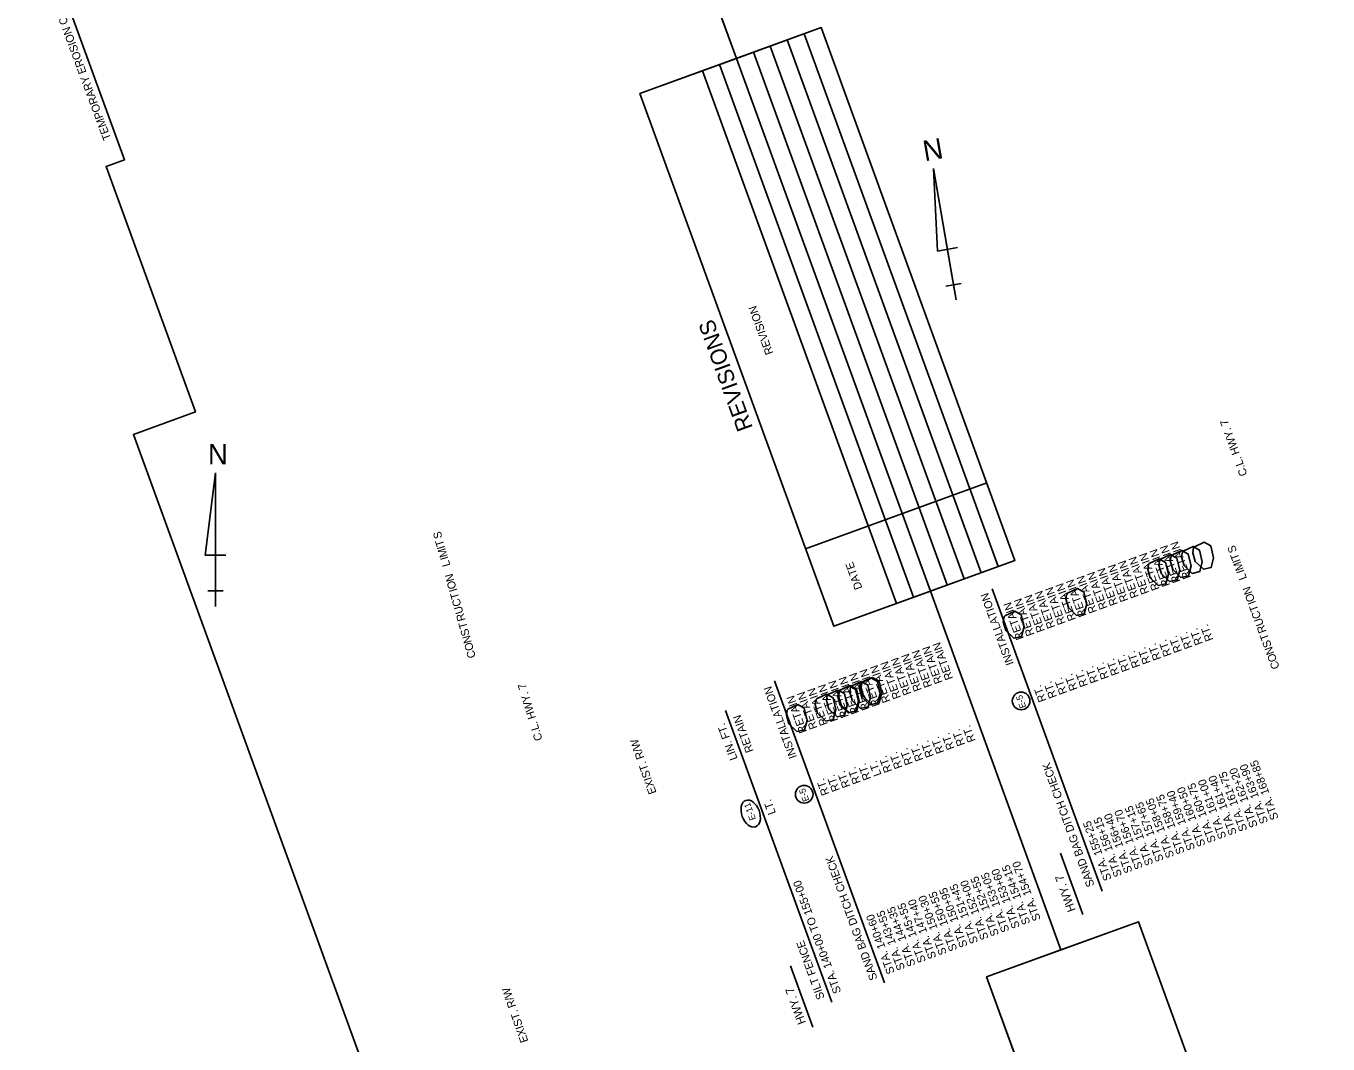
# Model space of a CAD drawing. Extents: x 986289 to 987754, y 1870781 to 1872971.
# Drawn here: x 986289 to 987265, y 1871771 to 1872534 of the extents above; entities that cross this region are included whole.
import ezdxf

# ---------------------------------------------------------------- set-up
doc = ezdxf.new("R2010")
doc.units = 0
for name, color, linetype in [('1', 7, 'Continuous'), ('44', 7, 'Continuous'), ('63', 7, 'Continuous'), ('Default', 7, 'Continuous'), ('NO PLOT', 7, 'Continuous'), ('R_Draft', 7, 'Continuous'), ('S_TREE', 7, 'Continuous')]:
    doc.layers.add(name, color=color, linetype=linetype)

msp = doc.modelspace()

# ---------------------------------------------------------------- linework, layer by layer
at = {"layer": '1'}
for p, q in [((986821.23, 1872510.15), (986718.28, 1872792.99)), ((987064.47, 1871841.86), (986966.59, 1872110.78)), ((987122.5, 1871862.99), (987008.75, 1871821.58)), ((987125.95, 1871499.59), (987008.75, 1871821.58))]:
    msp.add_line(p, q, dxfattribs=at)
msp.add_lwpolyline([(987207.82, 1871529.39), (987239.7, 1871540.99), (987122.5, 1871862.99)], dxfattribs=at)
for centre in [(987034.63, 1872028.46), (986872.01, 1871958.49)]:
    msp.add_circle(centre, 6.61, dxfattribs=at)
msp.add_ellipse((986831.89, 1871944.03), major_axis=(-3.6, 9.89), ratio=0.638788, dxfattribs=at)
at = {"layer": '44'}
for p, q in [((987095.25, 1871885.98), (987012.82, 1872112.45)), ((986932.24, 1871817.06), (986849.81, 1872043.53)), ((986892.62, 1871802.64), (986813, 1872021.4)), ((987080.79, 1871868.41), (987064.09, 1871914.31)), ((986878.55, 1871784.02), (986861.84, 1871829.92))]:
    msp.add_line(p, q, dxfattribs=at)
at = {"layer": '63'}
for p, q in [((986985.91, 1872329.1), (986969.03, 1872427.66)), ((986969.03, 1872427.66), (986982.01, 1872351.84)), ((986969.03, 1872427.66), (986971.83, 1872365.71)), ((986971.83, 1872365.71), (986987, 1872368.31)), ((986985.91, 1872329.1), (986982.01, 1872351.84)), ((986978.27, 1872339.5), (986989.65, 1872341.44)), ((986983.96, 1872340.47), (986978.27, 1872339.5)), ((986985.91, 1872329.1), (986983.96, 1872340.47)), ((986430.69, 1872199.39), (986422.99, 1872137.85)), ((986430.69, 1872099.39), (986430.69, 1872199.39)), ((986430.69, 1872199.39), (986430.69, 1872122.46)), ((986422.99, 1872137.85), (986438.38, 1872137.85)), ((986430.69, 1872099.39), (986430.69, 1872122.46)), ((986430.69, 1872110.93), (986424.92, 1872110.93)), ((986424.92, 1872110.93), (986436.46, 1872110.93)), ((986430.69, 1872099.39), (986430.69, 1872110.93))]:
    msp.add_line(p, q, dxfattribs=at)
at = {"layer": 'Default'}
for p, q in [((986748.87, 1872483.82), (986884.66, 1872533.24)), ((987017.33, 1872129.25), (986871.97, 1872528.62)), ((987030.02, 1872133.87), (986884.66, 1872533.24)), ((986991.96, 1872120.02), (986846.6, 1872519.39)), ((987004.65, 1872124.63), (986859.29, 1872524)), ((986966.59, 1872110.78), (986821.23, 1872510.15)), ((986979.27, 1872115.4), (986833.92, 1872514.77)), ((986979.27, 1872115.4), (986833.92, 1872514.77)), ((986941.22, 1872101.55), (986795.86, 1872500.92)), ((986953.9, 1872106.17), (986808.54, 1872505.53)), ((986894.23, 1872084.45), (986748.87, 1872483.82)), ((986873.09, 1872142.53), (987008.88, 1872191.95)), ((986894.23, 1872084.45), (987030.02, 1872133.87))]:
    msp.add_line(p, q, dxfattribs=at)
at = {"layer": 'NO PLOT'}
for points in [[(987753.66, 1871472.09), (987208.01, 1872971.24), (986718.28, 1872792.99), (986821.23, 1872510.15), (986884.66, 1872533.24), (987030.02, 1872133.87), (986966.59, 1872110.78), (987064.47, 1871841.86), (987122.5, 1871862.99), (987239.7, 1871540.99), (987181.66, 1871519.87), (987263.93, 1871293.85)], [(987753.66, 1871472.09), (987208.01, 1872971.24), (986718.28, 1872792.99), (986821.23, 1872510.15), (986884.66, 1872533.24), (987030.02, 1872133.87), (986966.59, 1872110.78), (987064.47, 1871841.86), (987122.5, 1871862.99), (987239.7, 1871540.99), (987181.66, 1871519.87), (987263.93, 1871293.85)], [(987753.66, 1871472.09), (987208.01, 1872971.24), (986718.28, 1872792.99), (986821.23, 1872510.15), (986884.66, 1872533.24), (987030.02, 1872133.87), (986966.59, 1872110.78), (987064.47, 1871841.86), (987122.5, 1871862.99), (987239.7, 1871540.99), (987181.66, 1871519.87), (987263.93, 1871293.85)], [(987753.66, 1871472.09), (987208.01, 1872971.24), (986718.28, 1872792.99), (986821.23, 1872510.15), (986884.66, 1872533.24), (987030.02, 1872133.87), (986966.59, 1872110.78), (987064.47, 1871841.86), (987122.5, 1871862.99), (987239.7, 1871540.99), (987181.66, 1871519.87), (987263.93, 1871293.85)], [(987753.66, 1871472.09), (987208.01, 1872971.24), (986718.28, 1872792.99), (986821.23, 1872510.15), (986884.66, 1872533.24), (987030.02, 1872133.87), (986966.59, 1872110.78), (987064.47, 1871841.86), (987122.5, 1871862.99), (987239.7, 1871540.99), (987181.66, 1871519.87), (987263.93, 1871293.85)], [(986774.2, 1871115.6), (986369.23, 1872228.25), (986415.65, 1872245.15), (986348.68, 1872429.14), (986362.4, 1872434.13), (986288.69, 1872636.64), (986718.28, 1872792.99), (986821.23, 1872510.15), (986748.87, 1872483.82), (986894.23, 1872084.45), (986966.59, 1872110.78), (987064.47, 1871841.86), (987008.75, 1871821.58), (987125.95, 1871499.59), (987181.66, 1871519.87), (987263.93, 1871293.85)], [(986774.2, 1871115.6), (986369.23, 1872228.25), (986415.65, 1872245.15), (986348.68, 1872429.14), (986362.4, 1872434.13), (986288.69, 1872636.64), (986718.28, 1872792.99), (986821.23, 1872510.15), (986748.87, 1872483.82), (986894.23, 1872084.45), (986966.59, 1872110.78), (987064.47, 1871841.86), (987008.75, 1871821.58), (987125.95, 1871499.59), (987181.66, 1871519.87), (987263.93, 1871293.85)], [(986774.2, 1871115.6), (986369.23, 1872228.25), (986415.65, 1872245.15), (986348.68, 1872429.14), (986362.4, 1872434.13), (986288.69, 1872636.64), (986718.28, 1872792.99), (986821.23, 1872510.15), (986748.87, 1872483.82), (986894.23, 1872084.45), (986966.59, 1872110.78), (987064.47, 1871841.86), (987008.75, 1871821.58), (987125.95, 1871499.59), (987181.66, 1871519.87), (987263.93, 1871293.85)], [(986774.2, 1871115.6), (986369.23, 1872228.25), (986415.65, 1872245.15), (986348.68, 1872429.14), (986362.4, 1872434.13), (986288.69, 1872636.64), (986718.28, 1872792.99), (986821.23, 1872510.15), (986748.87, 1872483.82), (986894.23, 1872084.45), (986966.59, 1872110.78), (987064.47, 1871841.86), (987008.75, 1871821.58), (987125.95, 1871499.59), (987181.66, 1871519.87), (987263.93, 1871293.85)], [(986774.2, 1871115.6), (986369.23, 1872228.25), (986415.65, 1872245.15), (986348.68, 1872429.14), (986362.4, 1872434.13), (986288.69, 1872636.64), (986718.28, 1872792.99), (986821.23, 1872510.15), (986748.87, 1872483.82), (986894.23, 1872084.45), (986966.59, 1872110.78), (987064.47, 1871841.86), (987008.75, 1871821.58), (987125.95, 1871499.59), (987181.66, 1871519.87), (987263.93, 1871293.85)]]:
    msp.add_lwpolyline(points, close=True, dxfattribs=at)
at = {"layer": 'S_TREE'}
for points in [[(987164.47, 1872143.94), (987171.94, 1872147.43), (987176.77, 1872144.69), (987178.92, 1872135.87), (987176.98, 1872128.48), (987171.28, 1872127.21), (987165.2, 1872133.1), (987163.34, 1872139.54), (987163.96, 1872143.2), (987165.15, 1872144.42)], [(987130.64, 1872131.63), (987138.11, 1872135.11), (987142.94, 1872132.38), (987145.09, 1872123.55), (987143.16, 1872116.17), (987137.45, 1872114.9), (987131.37, 1872120.78), (987129.51, 1872127.23), (987130.13, 1872130.88), (987131.32, 1872132.1)], [(987130.64, 1872131.63), (987138.11, 1872135.11), (987142.94, 1872132.38), (987145.09, 1872123.55), (987143.16, 1872116.17), (987137.45, 1872114.9), (987131.37, 1872120.78), (987129.51, 1872127.23), (987130.13, 1872130.88), (987131.32, 1872132.1)], [(987139.1, 1872134.71), (987146.57, 1872138.19), (987151.4, 1872135.46), (987153.55, 1872126.63), (987151.61, 1872119.25), (987145.91, 1872117.98), (987139.83, 1872123.86), (987137.97, 1872130.31), (987138.58, 1872133.96), (987139.78, 1872135.18)], [(987139.1, 1872134.71), (987146.57, 1872138.19), (987151.4, 1872135.46), (987153.55, 1872126.63), (987151.61, 1872119.25), (987145.91, 1872117.98), (987139.83, 1872123.86), (987137.97, 1872130.31), (987138.58, 1872133.96), (987139.78, 1872135.18)], [(987147.55, 1872137.79), (987155.03, 1872141.27), (987159.86, 1872138.54), (987162, 1872129.71), (987160.07, 1872122.33), (987154.37, 1872121.06), (987148.29, 1872126.94), (987146.43, 1872133.39), (987147.04, 1872137.04), (987148.24, 1872138.26)], [(987156.01, 1872140.86), (987163.48, 1872144.35), (987168.31, 1872141.62), (987170.46, 1872132.79), (987168.53, 1872125.41), (987162.82, 1872124.13), (987156.74, 1872130.02), (987154.89, 1872136.46), (987155.5, 1872140.12), (987156.69, 1872141.34)], [(987069.33, 1872109.32), (987076.81, 1872112.8), (987081.64, 1872110.07), (987083.79, 1872101.24), (987081.85, 1872093.86), (987076.15, 1872092.59), (987070.07, 1872098.47), (987068.21, 1872104.92), (987068.82, 1872108.57), (987070.02, 1872109.79)], [(987022.39, 1872092.23), (987029.87, 1872095.72), (987034.7, 1872092.98), (987036.85, 1872084.16), (987034.91, 1872076.77), (987029.21, 1872075.5), (987023.13, 1872081.39), (987021.27, 1872087.83), (987021.88, 1872091.49), (987023.08, 1872092.71)], [(986898.25, 1872036.27), (986905.72, 1872039.75), (986910.55, 1872037.02), (986912.7, 1872028.19), (986910.77, 1872020.81), (986905.06, 1872019.54), (986898.98, 1872025.42), (986897.13, 1872031.87), (986897.74, 1872035.52), (986898.93, 1872036.74)], [(986898.88, 1872036.5), (986906.35, 1872039.98), (986911.18, 1872037.25), (986913.33, 1872028.42), (986911.39, 1872021.04), (986905.69, 1872019.77), (986899.61, 1872025.65), (986897.75, 1872032.1), (986898.37, 1872035.75), (986899.56, 1872036.97)], [(986907.34, 1872039.57), (986914.81, 1872043.06), (986919.64, 1872040.33), (986921.79, 1872031.5), (986919.85, 1872024.12), (986914.15, 1872022.84), (986908.07, 1872028.73), (986906.21, 1872035.17), (986906.82, 1872038.83), (986908.02, 1872040.05)], [(986907.34, 1872039.57), (986914.81, 1872043.06), (986919.64, 1872040.33), (986921.79, 1872031.5), (986919.85, 1872024.12), (986914.15, 1872022.84), (986908.07, 1872028.73), (986906.21, 1872035.17), (986906.82, 1872038.83), (986908.02, 1872040.05)], [(986914.54, 1872042.2), (986922.01, 1872045.68), (986926.84, 1872042.95), (986928.99, 1872034.12), (986927.05, 1872026.74), (986921.35, 1872025.47), (986915.27, 1872031.35), (986913.41, 1872037.8), (986914.03, 1872041.45), (986915.22, 1872042.67)], [(986915.79, 1872042.65), (986923.27, 1872046.14), (986928.1, 1872043.4), (986930.24, 1872034.58), (986928.31, 1872027.19), (986922.61, 1872025.92), (986916.53, 1872031.81), (986914.67, 1872038.25), (986915.28, 1872041.91), (986916.47, 1872043.13)], [(986881.34, 1872030.11), (986888.81, 1872033.6), (986893.64, 1872030.86), (986895.79, 1872022.04), (986893.85, 1872014.65), (986888.15, 1872013.38), (986882.07, 1872019.27), (986880.21, 1872025.71), (986880.82, 1872029.37), (986882.02, 1872030.59)], [(986889.79, 1872033.19), (986897.27, 1872036.68), (986902.1, 1872033.94), (986904.24, 1872025.11), (986902.31, 1872017.73), (986896.61, 1872016.46), (986890.53, 1872022.34), (986888.67, 1872028.79), (986889.28, 1872032.44), (986890.48, 1872033.67)], [(986859.77, 1872022.26), (986867.24, 1872025.75), (986872.07, 1872023.01), (986874.22, 1872014.19), (986872.29, 1872006.8), (986866.58, 1872005.53), (986860.5, 1872011.42), (986858.64, 1872017.86), (986859.26, 1872021.52), (986860.45, 1872022.74)]]:
    msp.add_lwpolyline(points, dxfattribs=at)

# ---------------------------------------------------------------- texts
at = {"layer": '1'}
for s, height, rotation, p in [('TEMPORARY EROSION CONTROL DETAILS', 6, 110.32307, (986352.56, 1872450.06)), ('E-5 ', 4.8, 110, (987038.48, 1872024.01)), ('E-5 ', 4.8, 110, (986875.85, 1871954.04)), ('E-11', 4.8, 109.99998, (986835.88, 1871939.95))]:
    msp.add_text(s, height=height, rotation=rotation, dxfattribs=at).set_placement(p)
at = {"layer": '44'}
for s, height, rotation, p in [('RETAIN', 6, 110, (987154.17, 1872118.21)), ('RETAIN', 6, 110, (987162, 1872121.06)), ('RETAIN', 6, 110, (987130.68, 1872109.66)), ('RETAIN', 6, 110, (987138.51, 1872112.51)), ('RETAIN', 6, 110, (987146.38, 1872115.38)), ('RETAIN', 6, 110, (987099.44, 1872098.29)), ('RETAIN', 6, 110, (987107.23, 1872101.13)), ('RETAIN', 6, 110, (987115.06, 1872103.98)), ('RETAIN', 6, 110, (987122.89, 1872106.83)), ('RETAIN', 6, 110, (987075.95, 1872089.74)), ('RETAIN', 6, 110, (987083.74, 1872092.58)), ('RETAIN', 6, 110, (987091.61, 1872095.44)), ('INSTALLATION', 6, 110, (987029.21, 1872056.44)), ('RETAIN', 6, 110, (987052.5, 1872081.21)), ('RETAIN', 6, 110, (987060.29, 1872084.04)), ('RETAIN', 6, 110, (987068.12, 1872086.89)), ('RETAIN', 6, 110, (987036.84, 1872075.51)), ('RETAIN', 6, 110, (987044.67, 1872078.36)), ('RT.', 6, 110, (987155.35, 1872065.87)), ('RT.', 6, 110, (987163.18, 1872068.72)), ('RT.', 6, 110, (987170.97, 1872071.55)), ('RT.', 6, 110, (987178.8, 1872074.4)), ('RETAIN', 6, 110, (986968.09, 1872039.71)), ('RETAIN', 6, 110, (986975.88, 1872042.54)), ('RETAIN', 6, 110, (986983.71, 1872045.39)), ('RT.', 6, 110, (987131.86, 1872057.32)), ('RT.', 6, 110, (987139.69, 1872060.17)), ('RT.', 6, 110, (987147.52, 1872063.02)), ('RETAIN', 6, 110, (986944.64, 1872031.17)), ('RETAIN', 6, 110, (986952.43, 1872034.01)), ('RETAIN', 6, 110, (986960.26, 1872036.86)), ('RT.', 6, 110, (987100.58, 1872045.93)), ('RT.', 6, 110, (987108.41, 1872048.78)), ('RT.', 6, 110, (987116.24, 1872051.63)), ('RT.', 6, 110, (987124.03, 1872054.47)), ('RETAIN', 6, 110, (986921.15, 1872022.62)), ('RETAIN', 6, 110, (986928.94, 1872025.46)), ('RETAIN', 6, 110, (986936.81, 1872028.32)), ('RT.', 6, 110, (987077.09, 1872037.38)), ('RT.', 6, 110, (987084.92, 1872040.23)), ('RT.', 6, 110, (987092.75, 1872043.08)), ('INSTALLATION', 6, 110, (986866.58, 1871986.47)), ('RETAIN', 6, 110, (986889.87, 1872011.24)), ('RETAIN', 6, 110, (986897.66, 1872014.07)), ('RETAIN', 6, 110, (986905.49, 1872016.92)), ('RETAIN', 6, 110, (986913.32, 1872019.77)), ('RT.', 6, 110, (987053.64, 1872028.85)), ('RT.', 6, 110, (987061.47, 1872031.7)), ('RT.', 6, 110, (987069.3, 1872034.55)), ('RETAIN', 6, 110, (986874.21, 1872005.54)), ('RETAIN', 6, 110, (986882.04, 1872008.39)), ('RETAIN', 6, 109.99998, (986834.11, 1871990.94)), ('LIN. FT.', 6, 109.99998, (986822.17, 1871985.21)), ('RT.', 6, 110, (987000.55, 1871998.75)), ('RT.', 6, 110, (986969.24, 1871987.35)), ('RT.', 6, 110, (986977.07, 1871990.2)), ('RT.', 6, 110, (986984.9, 1871993.05)), ('RT.', 6, 110, (986992.73, 1871995.9)), ('RT.', 6, 110, (986945.79, 1871978.81)), ('RT.', 6, 110, (986953.62, 1871981.66)), ('RT.', 6, 110, (986961.45, 1871984.51)), ('RT.', 6, 110, (986914.47, 1871967.41)), ('RT.', 6, 110, (986922.3, 1871970.26)), ('LT.', 6, 110, (986930.08, 1871973.25)), ('RT.', 6, 110, (986937.96, 1871975.96)), ('SAND BAG DITCH CHECK', 6, 110, (987089.7, 1871890.25)), ('STA. 163+90', 6, 110, (987219.87, 1871937.63)), ('STA. 168+85', 6, 110, (987227.7, 1871940.48)), ('RT.', 6, 110, (986891.02, 1871958.88)), ('RT.', 6, 110, (986898.85, 1871961.73)), ('RT.', 6, 110, (986906.68, 1871964.58)), ('STA. 161+00', 6, 110, (987188.59, 1871926.25)), ('STA. 161+40', 6, 110, (987196.42, 1871929.1)), ('STA. 161+75', 6, 110, (987204.25, 1871931.95)), ('STA. 162+20', 6, 110, (987212.08, 1871934.8)), ('STA. 159+40', 6, 110, (987165.14, 1871917.71)), ('STA. 160+50', 6, 110, (987172.93, 1871920.55)), ('STA. 160+75', 6, 110, (987180.76, 1871923.4)), ('LT.', 6, 109.99998, (986850.87, 1871944.42)), ('STA. 157+15', 6, 110, (987133.82, 1871906.31)), ('STA. 157+65', 6, 110, (987141.65, 1871909.16)), ('STA. 158+05', 6, 110, (987149.48, 1871912.01)), ('STA. 158+75', 6, 110, (987157.31, 1871914.86)), ('STA. 156+15', 6, 110, (987110.37, 1871897.78)), ('STA. 156+40', 6, 110, (987118.2, 1871900.63)), ('STA. 156+70', 6, 110, (987125.99, 1871903.46)), ('STA. 155+25', 6, 110, (987102.54, 1871894.93)), ('SAND BAG DITCH CHECK', 6, 110, (986927.07, 1871820.28)), ('STA. 153+60', 6, 110, (987033.8, 1871859.13)), ('STA. 154+15', 6, 110, (987041.63, 1871861.98)), ('STA. 154+70', 6, 110, (987049.45, 1871864.83)), ('STA. 140+00 TO 155+00', 6, 109.99998, (986899.82, 1871810.36)), ('STA. 151+45', 6, 110, (987002.52, 1871847.74)), ('STA. 152+00', 6, 110, (987010.35, 1871850.59)), ('STA. 152+55', 6, 110, (987018.14, 1871853.43)), ('STA. 153+05', 6, 110, (987025.97, 1871856.28)), ('HWY. 7', 6.25, 110, (987075.58, 1871871.67)), ('STA. 150+30', 6, 110, (986979.03, 1871839.19)), ('STA. 150+55', 6, 110, (986986.86, 1871842.04)), ('STA. 150+95', 6, 110, (986994.69, 1871844.89)), ('STA. 143+55', 6, 110, (986947.75, 1871827.81)), ('STA. 144+35', 6, 110, (986955.58, 1871830.66)), ('STA. 145+55', 6, 110, (986963.37, 1871833.49)), ('STA. 147+40', 6, 110, (986971.2, 1871836.34)), ('STA. 140+60', 6, 110, (986939.92, 1871824.96)), ('SILT FENCE      ', 6, 109.99998, (986887.45, 1871805.86)), ('HWY. 7', 6.25, 110, (986873.34, 1871787.28))]:
    msp.add_text(s, height=height, rotation=rotation, dxfattribs=at).set_placement(p)
at = {"layer": '63'}
for rotation, p in [(9.71442, (986962.4, 1872433.03)), (360, (986425.05, 1872205.8))]:
    msp.add_text('N', height=15.38, rotation=rotation, dxfattribs=at).set_placement(p)
at = {"layer": 'Default'}
for s, height, p in [('REVISION', 6, (986848.94, 1872289.29)), ('REVISIONS', 12, (986833.67, 1872233.29)), ('DATE', 6, (986915.7, 1872113.17))]:
    msp.add_text(s, height=height, rotation=110, dxfattribs=at).set_placement(p)
at = {"layer": 'R_Draft'}
for s, rotation, p in [('C.L. HWY. 7', 109.95534, (987204.37, 1872198.23)), ('S', 104.08699, (986600.81, 1872150.84)), ('T', 106.70307, (986602.37, 1872145.2)), ('I', 106.70307, (986602.94, 1872143.29)), ('S', 110.16583, (987196.51, 1872140.7)), ('M', 107.48629, (986604.83, 1872137.15)), ('I', 106.22417, (986605.35, 1872135.24)), ('T', 110.17147, (987198.53, 1872135.2)), ('I', 110.17147, (987199.21, 1872133.34)), ('L', 105.52002, (986606.82, 1872130.06)), ('M', 110.16583, (987201.43, 1872127.3)), ('I', 110.16583, (987202.11, 1872125.44)), ('N', 104.97775, (986609.83, 1872118.78)), ('O', 104.97103, (986611.34, 1872113.12)), ('L', 110.16583, (987203.97, 1872120.39)), ('I', 106.4499, (986611.96, 1872111.24)), ('T', 105.77442, (986613.56, 1872105.6)), ('N', 110.16583, (987207.99, 1872109.43)), ('O', 110.16583, (987210.01, 1872103.93)), ('C', 105.77442, (986615.1, 1872100.14)), ('U', 106.20848, (986616.64, 1872094.59)), ('I', 110.16583, (987210.69, 1872102.07)), ('T', 110.16583, (987212.71, 1872096.57)), ('C', 110.17043, (987214.67, 1872091.25)), ('R', 105.73835, (986618.21, 1872089.12)), ('T', 105.73835, (986619.79, 1872083.5)), ('U', 110.17043, (987216.66, 1872085.84)), ('S', 105.83147, (986621.33, 1872078.05)), ('N', 105.7192, (986622.87, 1872072.59)), ('R', 110.16583, (987218.61, 1872080.52)), ('T', 110.16583, (987220.63, 1872075.02)), ('O', 105.22599, (986624.41, 1872066.94)), ('S', 110.16583, (987222.58, 1872069.7)), ('N', 110.16583, (987224.54, 1872064.38)), ('C', 105.8553, (986625.94, 1872061.48)), ('O', 110.17147, (987226.56, 1872058.88)), ('C', 110.16583, (987228.51, 1872053.56)), ('C.L. HWY. 7', 106.9707, (986675.9, 1871999.61)), ('EXIST. R/W', 109.29274, (986761.38, 1871959.77)), ('EXIST. R/W', 109.29274, (986665.29, 1871773.47))]:
    msp.add_text(s, height=6, rotation=rotation, dxfattribs=at).set_placement(p)

doc.saveas('drawing.dxf')
